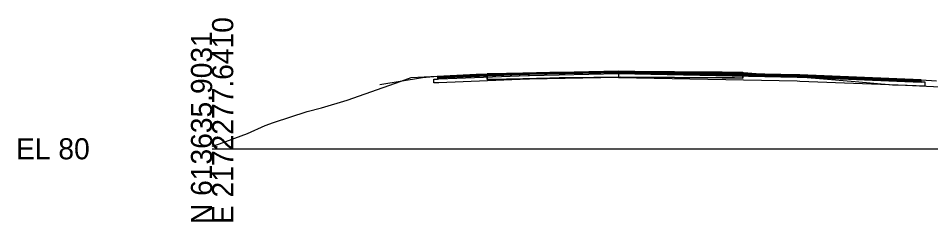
# Model space of a CAD drawing. Extents: x -26 to 1303, y -3010 to 12023.
# Drawn here: x -25.7 to 95.2, y 490.3 to 517.3 of the extents above; entities that cross this region are included whole.
import ezdxf

# ---------------------------------------------------------------- set-up
doc = ezdxf.new("R2010")
doc.units = 0
for name, color, linetype in [('RD_GPK_XS_Cell', 7, 'Continuous'), ('RD_XS_Base', 7, 'Continuous'), ('RD_XS_ExGround', 7, 'Continuous'), ('RD_XS_ExPaveRet', 7, 'Continuous'), ('RD_XS_Greenside', 7, 'Continuous'), ('RD_XS_Pave', 7, 'Continuous'), ('RD_XS_PaveOvlay_CP', 7, 'Continuous'), ('RD_XS_TieSlope', 7, 'Continuous')]:
    doc.layers.add(name, color=color, linetype=linetype)

msp = doc.modelspace()

# ---------------------------------------------------------------- linework, layer by layer
at = {"layer": 'RD_GPK_XS_Cell'}
msp.add_line((0, 500), (150, 500), dxfattribs=at)
at = {"layer": 'RD_XS_Base'}
for p, q in [((29.38, 508.75), (29.38, 509.24)), ((29.38, 509.24), (29.39, 509.24)), ((29.39, 509.24), (29.88, 509.26)), ((29.88, 509.26), (30.06, 509.27)), ((30.06, 509.27), (41.88, 509.74)), ((41.88, 509.24), (30.06, 508.77)), ((41.88, 509.74), (42.06, 509.75)), ((42.06, 509.25), (41.88, 509.24)), ((42.06, 509.75), (53.88, 509.98)), ((53.88, 509.48), (42.06, 509.25)), ((53.88, 509.98), (53.88, 510.14)), ((53.88, 510.14), (53.88, 509.49)), ((53.88, 509.98), (53.88, 509.49)), ((77.53, 509.51), (53.88, 509.98)), ((53.88, 509.98), (53.88, 509.98)), ((53.88, 509.49), (53.88, 509.48)), ((53.88, 509.49), (53.88, 509.48)), ((53.88, 509.48), (77.53, 509.01)), ((77.88, 509.5), (77.53, 509.51)), ((94, 508.86), (77.88, 509.5)), ((29.38, 508.74), (29.38, 508.75)), ((29.39, 508.74), (29.38, 508.74)), ((29.88, 508.76), (29.39, 508.74)), ((30.06, 508.77), (29.88, 508.76)), ((77.53, 509.01), (77.88, 509)), ((77.88, 509), (94.5, 508.34)), ((94.49, 508.84), (94, 508.86)), ((94.5, 508.84), (94.49, 508.84)), ((94.5, 508.34), (94.5, 508.84)), ((94.5, 508.34), (94.5, 508.34))]:
    msp.add_line(p, q, dxfattribs=at)
at = {"layer": 'RD_XS_ExGround'}
msp.add_lwpolyline([(0, 500.37), (0.96, 500.65), (4.69, 502.03), (7.02, 503.1), (8.12, 503.51), (12.59, 504.97), (14.51, 505.43), (17.9, 506.47), (25.08, 508.99), (26.4, 509.48), (35.02, 509.9), (36.47, 509.95), (38.93, 510), (39.4, 510.01), (45.98, 510.15), (54.12, 510.24), (70.18, 510.14), (70.34, 510.14), (70.43, 510.13), (79.98, 509.37), (80.13, 509.36), (80.5, 509.33), (85.24, 508.94), (90.19, 508.5), (91.89, 508.43), (100.21, 508.03)], dxfattribs=at)
at = {"layer": 'RD_XS_ExPaveRet'}
for points in [[(70.34, 510.14), (70.34, 510.14), (70.34, 509.8), (70.34, 509.39), (70.34, 509.39), (69.25, 509.4), (67.62, 509.41), (61.27, 509.45), (54.12, 509.49), (50.59, 509.45), (45.98, 509.4), (44.78, 509.37), (39.4, 509.26), (39.03, 509.25), (37.06, 509.21), (36.97, 509.21), (36.47, 509.2), (36.47, 509.61), (36.47, 509.95), (36.97, 509.96), (37.06, 509.96), (39.03, 510), (39.4, 510.01), (44.78, 510.12), (45.98, 510.15), (50.59, 510.2), (54.12, 510.24), (61.27, 510.2), (67.62, 510.16), (69.25, 510.15), (70.34, 510.14)], [(69.25, 510.15), (67.62, 510.16), (61.27, 510.2), (54.12, 510.24), (50.59, 510.2), (45.98, 510.15), (44.78, 510.12), (39.4, 510.01), (39.03, 510), (37.06, 509.96), (36.97, 509.96), (36.47, 509.95), (36.47, 509.61), (36.47, 509.2), (36.97, 509.21), (37.06, 509.21), (39.03, 509.25), (39.4, 509.26), (44.78, 509.37), (45.98, 509.4), (50.59, 509.45), (54.12, 509.49), (61.27, 509.45), (67.62, 509.41), (69.25, 509.4), (70.34, 509.39), (70.34, 509.8), (70.34, 510.14), (69.25, 510.15)]]:
    msp.add_lwpolyline(points, dxfattribs=at)
at = {"layer": 'RD_XS_Greenside'}
msp.add_line((27.88, 509.42), (22.24, 508.48), dxfattribs=at)
at = {"layer": 'RD_XS_Pave'}
for p, q in [((30.06, 509.59), (29.88, 509.58)), ((29.88, 509.58), (29.88, 509.42)), ((30.06, 509.43), (29.88, 509.42)), ((29.88, 509.42), (30.06, 509.43)), ((29.88, 509.42), (29.88, 509.26)), ((29.88, 509.42), (29.88, 509.42)), ((29.88, 509.26), (30.06, 509.27)), ((29.88, 509.26), (29.88, 509.26)), ((41.88, 510.06), (30.06, 509.59)), ((41.88, 509.9), (30.06, 509.43)), ((30.06, 509.43), (41.88, 509.9)), ((30.06, 509.27), (41.88, 509.74)), ((42.06, 510.06), (41.88, 510.06)), ((42.06, 509.9), (41.88, 509.9)), ((41.88, 509.9), (42.06, 509.9)), ((41.88, 509.74), (42.06, 509.75)), ((53.88, 510.3), (42.06, 510.06)), ((53.88, 510.14), (42.06, 509.9)), ((42.06, 509.9), (53.88, 510.14)), ((42.06, 509.75), (53.88, 509.98)), ((77.53, 509.83), (53.88, 510.3)), ((53.88, 509.98), (53.88, 510.14)), ((53.88, 510.14), (77.53, 509.67)), ((77.53, 509.67), (53.88, 510.14)), ((53.88, 510.14), (53.88, 509.98)), ((53.88, 509.98), (53.88, 509.98)), ((53.88, 509.98), (53.88, 509.98)), ((53.88, 509.98), (77.53, 509.51)), ((77.88, 509.82), (77.53, 509.83)), ((77.53, 509.67), (77.88, 509.66)), ((77.88, 509.66), (77.53, 509.67)), ((77.53, 509.51), (77.88, 509.5)), ((94, 509.17), (77.88, 509.82)), ((77.88, 509.66), (94, 509.02)), ((94, 509.02), (77.88, 509.66)), ((77.88, 509.5), (94, 508.86)), ((94, 509.02), (94, 509.17)), ((94, 509.02), (94, 509.02)), ((94, 508.86), (94, 509.02)), ((94, 508.86), (94, 508.86))]:
    msp.add_line(p, q, dxfattribs=at)
at = {"layer": 'RD_XS_PaveOvlay_CP'}
for p, q in [((29.88, 509.58), (41.88, 510.06)), ((41.88, 510.06), (53.88, 510.3)), ((53.88, 510.3), (77.88, 509.82)), ((77.88, 509.82), (94, 509.17))]:
    msp.add_line(p, q, dxfattribs=at)
at = {"layer": 'RD_XS_TieSlope'}
for p, q in [((29.88, 509.58), (27.88, 509.42)), ((94, 509.17), (96, 509.01))]:
    msp.add_line(p, q, dxfattribs=at)

# ---------------------------------------------------------------- texts
at = {"layer": 'RD_GPK_XS_Cell'}
for s, p in [('E 2172277.6410', (2.8, 490)), ('N 613635.9031', (0, 490))]:
    msp.add_text(s, height=2.8, rotation=90, dxfattribs=at).set_placement(p)
msp.add_text('EL 80', height=2.8, dxfattribs=at).set_placement((-26, 498.6))

doc.saveas('drawing.dxf')
